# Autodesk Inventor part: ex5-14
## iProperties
Shininess: 64.0
Length Units: 11272
Angle Units: 11279
Time Units: 11290
Mass Units: 11286
Length Display Precision: 3
Angle Display Precision: 2
Compacted: True
Part Number: ex5-14
Document SubType Name: Modeling
Created: 2002-09
Designer: Elise Moss
Density: 0.0
Volumn: 0.0
Area: 0.0
PropertySet Name: Model Information
Control State: 0
Master: False
Checked Out: False
Author: Elise Moss
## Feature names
1. Revolution1
2. Hole1
3. Shell1
4. Loft1
5. Sweep1
6. Coil1
7. Fillet1
8. Rib Chamfer [Chamfer]
